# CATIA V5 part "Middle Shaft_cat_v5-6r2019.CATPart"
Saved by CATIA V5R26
Part number: Middle shaft
Bounding box of the stored display mesh (mm): x 0 to 100, y -25 to 25, z -24.818 to 24.818
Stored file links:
  D:\_Deepak\CATIA\CATIA V5 2015 Parts Files\Tutorial Files\Tutorials\c16_catia_v5_6r2016_tut\CV joint\Middle Shaft_cat_v5-6r2012.CATPart
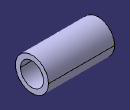
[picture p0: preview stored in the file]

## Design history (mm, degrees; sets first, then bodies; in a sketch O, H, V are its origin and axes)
Body1 (main body)
  Sketch1 on yz-plane, origin (0, 0, 0), H (0, 1, 0), V (0, 0, 1)
    circle A1 centre (0, 0) radius 25
    circle A2 centre (0, 0) radius 17.5
    radius A1 = 25
    radius A2 = 17.5
  Pad1: profile Sketch1, direction (1, 0, 0), length 100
